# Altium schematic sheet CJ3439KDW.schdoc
size 127 x 101 mm
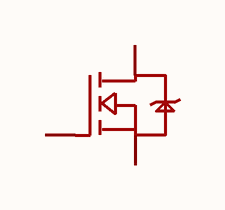
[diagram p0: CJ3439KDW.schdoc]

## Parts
Q?  cj3439kdw  [SOT-363_L2.1-W1.3-P0.65-LS2.3-BL]  (value not drawn)  (part A of 2)

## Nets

Not connected (* = marked no-connect by the designer): Q? 1(S1) 2(G1) 6(D1)

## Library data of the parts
Q? = cj3439kdw: 数量:1个N沟道+1个P沟道;漏源电压(Vdss):20V;连续漏极电流(Id):750mA；660mA;导通电阻(RDS(on)):380mΩ@4.5V;耗散功率(Pd):-;阈值电压(Vgs(th)):350mV;; Manufacturer: CJ(江苏长电/长晶); AddInBom: yes; ModelId: 865e910eee9742ff86c36441d8b3608e; ModelTransform: 82.677,90.551,0,0,0,0,0,0,0; Drain to Source Voltage: 20V; Gate Threshold Voltage (Vgs(th)): 350mV; Input Capacitance(Ciss): 120pF; Reverse Transfer Capacitance (Crss@Vds): 15pF; Type: N沟道+P沟道; Output Capacitance(Coss): 15pF；13pF; Vgs: ±12V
